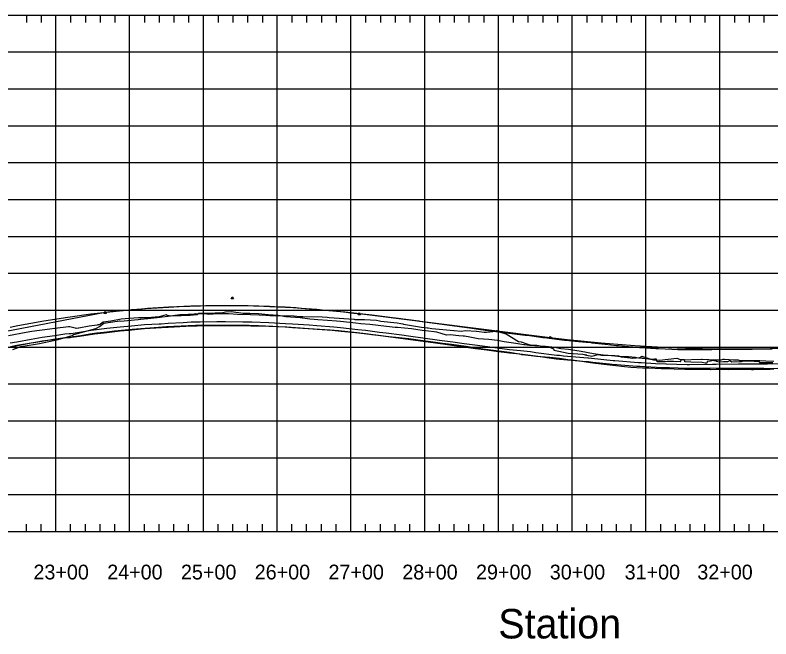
# Model space of a CAD drawing. Extents: x 704797 to 712284, y 374940 to 376945.
# Drawn here: x 709378 to 710403, y 375080 to 375925 of the extents above; entities that cross this region are included whole.
import ezdxf

# ---------------------------------------------------------------- set-up
doc = ezdxf.new("R2010")
doc.units = 0
for name, color, linetype in [('1', 7, 'Continuous'), ('10', 7, 'Continuous'), ('12', 7, 'Continuous'), ('13', 7, 'Continuous'), ('48', 7, 'Continuous'), ('61', 7, 'Continuous'), ('Existing', 7, 'Continuous')]:
    doc.layers.add(name, color=color, linetype=linetype)

msp = doc.modelspace()

# ---------------------------------------------------------------- linework, layer by layer
for points in [[(709672.8, 375543.7), (709674.3, 375540.7), (709671.3, 375540.7)], [(709500.5, 375524.2), (709502, 375521.2), (709499, 375521.2)], [(709845, 375522.3), (709846.5, 375519.3), (709843.5, 375519.3)], [(710104, 375490.1), (710105.5, 375487.1), (710102.5, 375487.1)]]:
    msp.add_lwpolyline(points, close=True)
at = {"layer": '10'}
for points in [[(710405.5, 375454.1), (710393.5, 375453.9), (710387.9, 375453.9), (710387.8, 375454.5), (710387.4, 375455.9), (710385.3, 375455.8), (710384.3, 375455.8), (710380.7, 375455.9), (710379.4, 375456.3), (710376.9, 375456.2), (710369.3, 375456.3), (710365.8, 375456.3), (710363, 375455.4), (710350.1, 375455.1), (710347.4, 375456.7), (710346.7, 375456.7), (710346.1, 375456.5), (710344.2, 375455.3), (710342.9, 375455.3), (710339, 375455.3), (710333.1, 375455.2), (710329.8, 375456), (710328.8, 375456.3), (710326.6, 375456.9), (710326.3, 375457), (710325.7, 375457.2), (710325.1, 375457.2), (710324.6, 375457.2), (710321, 375456.5), (710317.5, 375456), (710316.8, 375455.9), (710316.7, 375455.5), (710316.2, 375453.6), (710314.1, 375453.6), (710309.9, 375454.4), (710294.5, 375455.1), (710286.5, 375455.3), (710286.4, 375455.6), (710286.3, 375456), (710285.9, 375458), (710284.6, 375458.2), (710283.8, 375458.3), (710282.8, 375458.4), (710280.9, 375458.3), (710280.4, 375456), (710280.4, 375455.7), (710280.3, 375455.6), (710271.2, 375455.9), (710262.5, 375455.8), (710259.7, 375455.4), (710251.2, 375455.5), (710248.9, 375455.5), (710248.7, 375455.6), (710248.5, 375456.6), (710248, 375458.3), (710247.8, 375458.9), (710247.6, 375459), (710246.9, 375459.1), (710246.6, 375459), (710246.1, 375459), (710245.3, 375459), (710245.1, 375459), (710241.1, 375458.6), (710240.1, 375458.8), (710238.8, 375459), (710237.3, 375459.2), (710230.4, 375459.8), (710228.7, 375459.9), (710225.6, 375460.4), (710223.4, 375460.5), (710221.3, 375460.9), (710219.7, 375461.3), (710210, 375462.3), (710209.3, 375462.4), (710209.1, 375462.4), (710209, 375462.4), (710208.8, 375462.4), (710202.5, 375462.1), (710201.9, 375462.1), (710201.4, 375462.1), (710201, 375462.1), (710200.6, 375462.1), (710200.3, 375462.1), (710182.4, 375463.9), (710181.6, 375463.9), (710181, 375464), (710175.8, 375464.7), (710162.7, 375466.5), (710145.8, 375469.6), (710128.9, 375472), (710118.2, 375473), (710109.9, 375474.9), (710106, 375475.4), (710105.7, 375475.4), (710097.5, 375476.2), (710076, 375477.4), (710069.7, 375478.3), (710068.1, 375478.3), (710057.5, 375480.4), (710041.7, 375482.4), (710032.5, 375484.3), (710020.7, 375485.8), (710006.4, 375486.8), (709995.1, 375489), (709987.5, 375490.1), (709985.7, 375490.4), (709980, 375490.9), (709968.2, 375492.2), (709963.1, 375491.7), (709950.4, 375495.7), (709935.4, 375497.4), (709930.3, 375497.8), (709915.9, 375500.1), (709896.7, 375502.1), (709893.9, 375501.8), (709893.6, 375501.9), (709882.1, 375503.5), (709870.8, 375504.6), (709859.3, 375505.9), (709847, 375507.2), (709840.6, 375507.9), (709819.4, 375510.1), (709814, 375510.6), (709801.9, 375511.5), (709788.8, 375512.5), (709783.8, 375512.8), (709777.8, 375513.2), (709765.1, 375515.1), (709745.3, 375516.6), (709735.3, 375518.3), (709721.5, 375519), (709708.3, 375520.5), (709696.8, 375521), (709687.7, 375521), (709671.2, 375523.2), (709663.8, 375522.7), (709658.3, 375521.4), (709649.8, 375521.4), (709627.2, 375521.2), (709625.1, 375519), (709615.8, 375518.5), (709603.9, 375518.1), (709602.9, 375518), (709590.3, 375517.4), (709584.5, 375518.2), (709583.1, 375519), (709573.9, 375516.5), (709557.8, 375515.2), (709545.9, 375515), (709533.1, 375514.2), (709522.3, 375513.1), (709508, 375510.8), (709497.9, 375509.2), (709497.7, 375509.2), (709494, 375506.6), (709492.2, 375505.6), (709490.4, 375505.4), (709489.6, 375505.2), (709479, 375503.7), (709464.7, 375501.2), (709464.3, 375501.2), (709461.3, 375500.5), (709460.4, 375501), (709458.2, 375501.6), (709452.8, 375503.1), (709450.8, 375502.8), (709432.4, 375500.5), (709425.7, 375499.6), (709401, 375496.4), (709393.5, 375495.2), (709369.5, 375490.7)], [(709375.2, 375472.3), (709386.3, 375476.2), (709389.3, 375476.6), (709411.6, 375480.5), (709424.1, 375483.1), (709437, 375485.6), (709455.7, 375491.3), (709457.7, 375492.3), (709458.1, 375492.4), (709487.8, 375500.8), (709489.8, 375501.5), (709493, 375503.2), (709498.8, 375507.7), (709517, 375510.4), (709517.2, 375510.5), (709519.8, 375510.9), (709521.3, 375510.8), (709545.4, 375513), (709547.9, 375513.1), (709549.1, 375513.2), (709558.5, 375514.3), (709575, 375516.2), (709577.7, 375516.5), (709585.8, 375517.2), (709601.7, 375519.6), (709604.6, 375519.8), (709621, 375520.5), (709623.1, 375520.8), (709638.3, 375520.6), (709641.3, 375520.3), (709653.5, 375520.9), (709667.3, 375520.8), (709667.6, 375520.8), (709680.1, 375520), (709697.6, 375519.6), (709709.1, 375519.4), (709718.5, 375518.8), (709723.7, 375518.5), (709724, 375518.5), (709733.5, 375518.4), (709756.1, 375517.6), (709764.6, 375517.1), (709768.3, 375517.1), (709794.6, 375516.3), (709801.3, 375515.8), (709804, 375515.6), (709837.5, 375513.1), (709838.2, 375513.1), (709839, 375513), (709841.4, 375512.7), (709852.3, 375512.7), (709868.4, 375511.9), (709872.5, 375511), (709874.2, 375510.8), (709896.6, 375508.3), (709901.3, 375507.6), (709903.9, 375507.1), (709905, 375506.7), (709929.2, 375502.3), (709936.9, 375501.7), (709938.6, 375501.4), (709943.6, 375500.6), (709973.1, 375497.8), (709973.9, 375498), (709983.1, 375496.9), (709989, 375497.9), (710003.8, 375497), (710007.5, 375496.4), (710014.4, 375495.6), (710017.7, 375495.6), (710030.5, 375497.1), (710031.6, 375498.1), (710031.9, 375498), (710033.1, 375496.4), (710042.3, 375494), (710044, 375493.2), (710045.7, 375492.7), (710053.5, 375487.4), (710058.5, 375484.5), (710060.7, 375483.2), (710064.5, 375482.8), (710072.3, 375479.7), (710075, 375479.1), (710077.2, 375478.5), (710084.3, 375478.2), (710085.6, 375478), (710096.7, 375476), (710097, 375476.5), (710099.9, 375475.5), (710101.9, 375475.8), (710108.5, 375473), (710108.7, 375471.7), (710108.8, 375471.1), (710115.5, 375469.8), (710128.1, 375467.3), (710148.3, 375465.9), (710150.1, 375465.4), (710151.2, 375465.1), (710152.1, 375464.8), (710152.2, 375464.8), (710152.2, 375464.8), (710152.4, 375465.2), (710152.6, 375465.5), (710153.1, 375464.7), (710153.2, 375464.5), (710160.2, 375463.3), (710168.9, 375465.2), (710173.3, 375464.7), (710178.4, 375464.4), (710191.3, 375464.1), (710196.7, 375463.6), (710200.3, 375462.3), (710201, 375462.3), (710215.7, 375460.6), (710225.4, 375461.3), (710228.3, 375463.2), (710240.5, 375459.3), (710244, 375458), (710252, 375457.6), (710275.7, 375460.3), (710275.7, 375460.3), (710281.5, 375458.3), (710308.8, 375459.2), (710309.5, 375459.2), (710310.1, 375459.1), (710328.1, 375458.4), (710335.7, 375458.1), (710338.5, 375459.2), (710340.4, 375459.1), (710346.6, 375458.8), (710352.4, 375458.4), (710358.7, 375458.1), (710360.7, 375457.5), (710366.8, 375457.2), (710369.6, 375457.3), (710386.1, 375457.4), (710388.1, 375457.4), (710396, 375456.9), (710407.1, 375456.3)]]:
    msp.add_lwpolyline(points, dxfattribs=at)
at = {"layer": '12'}
for points in [[(709371.9, 375481.1), (709380.6, 375482.8), (709400.4, 375486.2), (709415, 375488.9), (709432.1, 375491.2), (709446, 375493.3), (709451.6, 375493.7), (709452.9, 375493.8), (709454.3, 375494.1), (709468.4, 375496.2), (709484.1, 375498.7), (709485.3, 375498.9), (709503, 375500.9), (709520.9, 375502.9), (709536.1, 375504.1), (709553.9, 375506), (709573.6, 375507.1), (709576.5, 375507.2), (709586.1, 375507.8), (709606.4, 375509), (709617.2, 375509.5), (709629.2, 375509.7), (709652, 375510.1), (709663.8, 375510), (709687.4, 375509.8), (709699.4, 375509.5), (709722.6, 375508.9), (709744.8, 375507.6), (709754.6, 375507.1), (709777.1, 375505.6), (709787.7, 375504.7), (709810.4, 375502.8), (709819.7, 375502), (709842.9, 375499.4), (709853.4, 375498.2), (709872.5, 375495.9), (709881.5, 375494.8), (709902.9, 375491.9), (709911.7, 375490.7), (709953.8, 375485), (709964.7, 375483.5), (709971.7, 375482.5), (709971.8, 375482.5), (709987.4, 375480.5), (710001.6, 375478.6), (710018.9, 375476.2), (710032.1, 375474.6), (710048.9, 375472.4), (710063.5, 375470.9), (710077.1, 375469.4), (710084.2, 375468.3), (710112.7, 375464.6), (710116, 375464.4), (710116.4, 375464.5), (710116.7, 375464.3), (710122, 375463.8), (710149.7, 375461.4), (710155, 375461.1), (710155.4, 375461), (710155.7, 375460.9), (710159.8, 375460.5), (710189.4, 375457.5), (710191.6, 375457.3), (710223.6, 375454.5), (710224.6, 375454.5), (710227, 375454.4), (710246.7, 375453.4), (710260.6, 375452.7), (710261.5, 375452.7), (710289.4, 375451.9), (710292.7, 375451.9), (710324.1, 375452.4), (710328.9, 375452.4), (710359.1, 375452.6), (710365.6, 375452.6), (710384, 375452.7), (710392, 375452.8), (710398.4, 375452.9), (710414.3, 375453.1)], [(709372.3, 375476.2), (709380.6, 375477.9), (709400.2, 375481.2), (709410.4, 375483.1), (709415, 375483.9), (709433.1, 375486.1), (709445.5, 375488), (709451.8, 375488.3), (709453.3, 375488.4), (709454.9, 375488.9), (709465.9, 375490.4), (709486.3, 375493.5), (709499.1, 375494.9), (709521.1, 375497.5), (709532.1, 375498.4), (709553.7, 375500.7), (709577.1, 375501.9), (709585.9, 375502.5), (709610.1, 375503.8), (709617.4, 375504.2), (709624.5, 375504.3), (709625.2, 375504.3), (709652.2, 375504.9), (709661.1, 375504.8), (709687.5, 375504.6), (709698.1, 375504.4), (709722.5, 375503.9), (709744.4, 375502.7), (709754.6, 375502.1), (709775.6, 375500.8), (709788.1, 375499.8), (709808.2, 375498.2), (709820.5, 375497.2), (709839.8, 375495.1), (709855.2, 375493.4), (709862.1, 375492.6), (709870.3, 375491.6), (709884, 375489.9), (709901.1, 375487.5), (709914.4, 375485.8), (709948.6, 375481.1), (709964.6, 375478.9), (709970.3, 375478.1), (709983.6, 375476.3), (710002.7, 375473.7), (710017.8, 375471.6), (710033.7, 375469.6), (710048.9, 375467.6), (710062.7, 375466.1), (710077.2, 375464.4), (710083.8, 375463.4), (710112.1, 375459.6), (710115.6, 375459.4), (710116, 375459.5), (710116.4, 375459.3), (710122.2, 375458.7), (710147.6, 375456.5), (710154.9, 375456), (710155.5, 375455.8), (710155.8, 375455.7), (710161.9, 375455.1), (710184.1, 375452.9), (710187.7, 375452.5), (710194, 375451.9), (710221.2, 375449.5), (710225.9, 375449.4), (710255.1, 375447.9), (710260.6, 375447.6), (710265.6, 375447.7), (710288.9, 375447), (710295.1, 375446.8), (710321.4, 375447.2), (710329.1, 375446.9), (710348.3, 375446.9), (710353.7, 375446.9), (710364.1, 375446.8), (710371, 375446.8), (710393.5, 375446.9), (710398.3, 375446.5), (710399.3, 375446.5), (710412.7, 375446.7)]]:
    msp.add_lwpolyline(points, dxfattribs=at)
at = {"layer": '13'}
msp.add_lwpolyline([(710407.2, 375445.3), (710402.2, 375445.2), (710401.5, 375445.1), (710379.6, 375444.9), (710379, 375444.8), (710378.8, 375444.8), (710377.9, 375444.7), (710377.2, 375444.6), (710376.6, 375444.7), (710369.7, 375445), (710346.1, 375444.8), (710339.9, 375445), (710321.7, 375444.8), (710320.9, 375444.9), (710311.8, 375445.1), (710304.3, 375445.1), (710294.9, 375445.1), (710286.2, 375445.2), (710272, 375445.7), (710263.8, 375445.8), (710254.2, 375446.2), (710237.8, 375446.8), (710237.1, 375446.8), (710231, 375446.9), (710230, 375446.9), (710228.9, 375446.9), (710213, 375447.9), (710204.8, 375448.9), (710189, 375450.7), (710176.8, 375451.9), (710161.6, 375453.7), (710146.6, 375455.9), (710133.6, 375457.6), (710127.9, 375458.3), (710116.4, 375459.8), (710103.2, 375461.5), (710102.9, 375461.5), (710085.3, 375462.5), (710066.9, 375464.9), (710065.6, 375464.9), (710064.4, 375465.2), (710048.7, 375468.3), (710030.8, 375470.5), (710012.6, 375472.8), (709989.9, 375476.2), (709970.1, 375479), (709958, 375480.5), (709945.1, 375482.3), (709928.1, 375484.6), (709912.4, 375486.5), (709894.6, 375488.4), (709885.3, 375489.5), (709849.9, 375493.8), (709838, 375495.2), (709816.8, 375497.3), (709805.6, 375498.3), (709783.9, 375499.7), (709770.8, 375500.8), (709746.8, 375502.5), (709735.6, 375503.1), (709727.8, 375503.5), (709708.4, 375504.4), (709695.6, 375504.7), (709672.1, 375504.8), (709659.4, 375504.9), (709635.5, 375504.9), (709623.4, 375504.7), (709623.2, 375504.6), (709593.5, 375503.5), (709583.6, 375502.9), (709572.8, 375502.2), (709548.7, 375500.3), (709537.1, 375499.4), (709513.4, 375497.1), (709502.8, 375495.8), (709490, 375494.3), (709489.3, 375494.2), (709479.9, 375492.9), (709467.6, 375490.7), (709457.3, 375489.2), (709455.9, 375488.9), (709454.2, 375488.5), (709452.7, 375488.7), (709430.6, 375485.7), (709420, 375484.1), (709403.7, 375481.1), (709400.4, 375480.6), (709389.1, 375478.5), (709367.6, 375474.3)], dxfattribs=at)
at = {"layer": '48'}
for p, q in [((709177, 375460.6), (709500.5, 375522.7)), ((709845, 375520.8), (710104, 375488.6))]:
    msp.add_line(p, q, dxfattribs=at)
for points in [[(709500.5, 375522.7), (709507.7, 375523.5), (709514.9, 375524.2), (709522.1, 375524.9), (709529.3, 375525.6), (709536.4, 375526.3), (709543.6, 375526.9), (709550.8, 375527.5), (709558, 375528), (709565.1, 375528.5), (709572.3, 375529), (709579.5, 375529.5), (709586.7, 375529.9), (709593.8, 375530.2), (709601, 375530.6), (709608.2, 375530.9), (709615.4, 375531.1), (709622.5, 375531.3), (709629.7, 375531.5), (709636.9, 375531.7), (709644.1, 375531.8), (709651.2, 375531.9), (709658.4, 375532), (709665.6, 375532), (709679.9, 375531.9), (709687.1, 375531.8), (709694.3, 375531.7), (709701.5, 375531.5), (709708.7, 375531.3), (709715.8, 375531.1), (709723, 375530.8), (709730.2, 375530.5), (709737.4, 375530.1), (709744.5, 375529.8), (709751.7, 375529.4), (709758.9, 375528.9), (709766.1, 375528.4), (709773.2, 375527.9), (709780.4, 375527.4), (709787.6, 375526.8), (709794.8, 375526.1), (709801.9, 375525.5), (709809.1, 375524.8), (709816.3, 375524.1), (709823.5, 375523.3), (709830.6, 375522.5), (709837.8, 375521.6), (709845, 375520.8)], [(710104, 375488.6), (710126.9, 375485.9), (710149.9, 375483.4), (710172.8, 375481.2), (710195.7, 375479.3), (710218.6, 375477.6), (710241.5, 375476.2), (710264.4, 375475.1), (710287.4, 375474.2), (710310.3, 375473.5), (710333.2, 375473.2), (710356.1, 375473.1), (710379, 375473.2), (710401.9, 375473.6), (710424.9, 375474.3)]]:
    msp.add_lwpolyline(points, dxfattribs=at)
at = {"layer": '61'}
for p, q in [((708133.7, 375925.5), (712133.7, 375925.5)), ((709393.7, 375925.5), (709393.7, 375915.5)), ((709413.7, 375925.5), (709413.7, 375915.5)), ((709433.7, 375225.5), (709433.7, 375925.5)), ((709453.7, 375925.5), (709453.7, 375915.5)), ((709473.7, 375925.5), (709473.7, 375915.5)), ((709493.7, 375925.5), (709493.7, 375915.5)), ((709513.7, 375925.5), (709513.7, 375915.5)), ((709533.7, 375225.5), (709533.7, 375925.5)), ((709553.7, 375925.5), (709553.7, 375915.5)), ((709573.7, 375925.5), (709573.7, 375915.5)), ((709593.7, 375925.5), (709593.7, 375915.5)), ((709613.7, 375925.5), (709613.7, 375915.5)), ((709633.7, 375225.5), (709633.7, 375925.5)), ((709653.7, 375925.5), (709653.7, 375915.5)), ((709673.7, 375925.5), (709673.7, 375915.5)), ((709693.7, 375925.5), (709693.7, 375915.5)), ((709713.7, 375925.5), (709713.7, 375915.5)), ((709733.7, 375225.5), (709733.7, 375925.5)), ((709753.7, 375925.5), (709753.7, 375915.5)), ((709773.7, 375925.5), (709773.7, 375915.5)), ((709793.7, 375925.5), (709793.7, 375915.5)), ((709813.7, 375925.5), (709813.7, 375915.5)), ((709833.7, 375225.5), (709833.7, 375925.5)), ((709853.7, 375925.5), (709853.7, 375915.5)), ((709873.7, 375925.5), (709873.7, 375915.5)), ((709893.7, 375925.5), (709893.7, 375915.5)), ((709913.7, 375925.5), (709913.7, 375915.5)), ((709933.7, 375225.5), (709933.7, 375925.5)), ((709953.7, 375925.5), (709953.7, 375915.5)), ((709973.7, 375925.5), (709973.7, 375915.5)), ((709993.7, 375925.5), (709993.7, 375915.5)), ((710013.7, 375925.5), (710013.7, 375915.5)), ((710033.7, 375225.5), (710033.7, 375925.5)), ((710053.7, 375925.5), (710053.7, 375915.5)), ((710073.7, 375925.5), (710073.7, 375915.5)), ((710093.7, 375925.5), (710093.7, 375915.5)), ((710113.7, 375925.5), (710113.7, 375915.5)), ((710133.7, 375225.5), (710133.7, 375925.5)), ((710153.7, 375925.5), (710153.7, 375915.5)), ((710173.7, 375925.5), (710173.7, 375915.5)), ((710193.7, 375925.5), (710193.7, 375915.5)), ((710213.7, 375925.5), (710213.7, 375915.5)), ((710233.7, 375225.5), (710233.7, 375925.5)), ((710253.7, 375925.5), (710253.7, 375915.5)), ((710273.7, 375925.5), (710273.7, 375915.5)), ((710293.7, 375925.5), (710293.7, 375915.5)), ((710313.7, 375925.5), (710313.7, 375915.5)), ((710333.7, 375225.5), (710333.7, 375925.5)), ((710353.7, 375925.5), (710353.7, 375915.5)), ((710373.7, 375925.5), (710373.7, 375915.5)), ((710393.7, 375925.5), (710393.7, 375915.5)), ((708133.7, 375875.5), (712133.7, 375875.5)), ((708133.7, 375825.5), (712133.7, 375825.5)), ((708133.7, 375775.5), (712133.7, 375775.5)), ((708133.7, 375725.5), (712133.7, 375725.5)), ((708133.7, 375675.5), (712133.7, 375675.5)), ((708133.7, 375625.5), (712133.7, 375625.5)), ((708133.7, 375575.5), (712133.7, 375575.5)), ((708133.7, 375525.5), (712133.7, 375525.5)), ((708133.7, 375475.5), (712133.7, 375475.5)), ((708133.7, 375425.5), (712133.7, 375425.5)), ((708133.7, 375375.5), (712133.7, 375375.5)), ((708133.7, 375325.5), (712133.7, 375325.5)), ((708133.7, 375275.5), (712133.7, 375275.5)), ((709393.7, 375225.5), (709393.7, 375235.5)), ((709413.7, 375225.5), (709413.7, 375235.5)), ((709453.7, 375225.5), (709453.7, 375235.5)), ((709473.7, 375225.5), (709473.7, 375235.5)), ((709493.7, 375225.5), (709493.7, 375235.5)), ((709513.7, 375225.5), (709513.7, 375235.5)), ((709553.7, 375225.5), (709553.7, 375235.5)), ((709573.7, 375225.5), (709573.7, 375235.5)), ((709593.7, 375225.5), (709593.7, 375235.5)), ((709613.7, 375225.5), (709613.7, 375235.5)), ((709653.7, 375225.5), (709653.7, 375235.5)), ((709673.7, 375225.5), (709673.7, 375235.5)), ((709693.7, 375225.5), (709693.7, 375235.5)), ((709713.7, 375225.5), (709713.7, 375235.5)), ((709753.7, 375225.5), (709753.7, 375235.5)), ((709773.7, 375225.5), (709773.7, 375235.5)), ((709793.7, 375225.5), (709793.7, 375235.5)), ((709813.7, 375225.5), (709813.7, 375235.5)), ((709853.7, 375225.5), (709853.7, 375235.5)), ((709873.7, 375225.5), (709873.7, 375235.5)), ((709893.7, 375225.5), (709893.7, 375235.5)), ((709913.7, 375225.5), (709913.7, 375235.5)), ((709953.7, 375225.5), (709953.7, 375235.5)), ((709973.7, 375225.5), (709973.7, 375235.5)), ((709993.7, 375225.5), (709993.7, 375235.5)), ((710013.7, 375225.5), (710013.7, 375235.5)), ((710053.7, 375225.5), (710053.7, 375235.5)), ((710073.7, 375225.5), (710073.7, 375235.5)), ((710093.7, 375225.5), (710093.7, 375235.5)), ((710113.7, 375225.5), (710113.7, 375235.5)), ((710153.7, 375225.5), (710153.7, 375235.5)), ((710173.7, 375225.5), (710173.7, 375235.5)), ((710193.7, 375225.5), (710193.7, 375235.5)), ((710213.7, 375225.5), (710213.7, 375235.5)), ((710253.7, 375225.5), (710253.7, 375235.5)), ((710273.7, 375225.5), (710273.7, 375235.5)), ((710293.7, 375225.5), (710293.7, 375235.5)), ((710313.7, 375225.5), (710313.7, 375235.5)), ((710353.7, 375225.5), (710353.7, 375235.5)), ((710373.7, 375225.5), (710373.7, 375235.5)), ((710393.7, 375225.5), (710393.7, 375235.5)), ((708133.7, 375225.5), (712133.7, 375225.5))]:
    msp.add_line(p, q, dxfattribs=at)
at = {"layer": 'Existing'}
msp.add_lwpolyline([(709371.6, 375502.6), (709382.1, 375504.6), (709382.2, 375504.7), (709417.5, 375511.2), (709417.5, 375511.2), (709450, 375516.1), (709450.1, 375516.1), (709450.1, 375516.1), (709450.1, 375516.1), (709450.1, 375516.1), (709481.3, 375520.5), (709481.3, 375520.5), (709481.3, 375520.5), (709481.3, 375520.5), (709519.8, 375524.8), (709554.6, 375527.6), (709555.1, 375527.7), (709587, 375529.7), (709597.6, 375530.3), (709616.5, 375531.2), (709649.6, 375531.9), (709650.4, 375531.9), (709684.9, 375531.7), (709686, 375531.7), (709722.1, 375530.8), (709723.1, 375530.8), (709724, 375530.7), (709755.6, 375528.9), (709756.4, 375528.9), (709792.4, 375525.9), (709793.1, 375525.9), (709825.1, 375523.1), (709825.4, 375523.1), (709862.1, 375519), (709862.1, 375519), (709893.8, 375515.2), (709894.2, 375515.1), (709925.7, 375511), (709926.7, 375510.8), (709964.1, 375505.6), (709964.2, 375505.6), (709964.3, 375505.6), (709997.8, 375501), (710009.2, 375499.4), (710010, 375499.3), (710015.8, 375498.6), (710033.9, 375496.3), (710047.6, 375494.5), (710048.2, 375494.5), (710048.7, 375494.4), (710049.7, 375494.3), (710052, 375494), (710070.1, 375491.7), (710075.6, 375491), (710088.1, 375489.4), (710094.1, 375488.6), (710095.1, 375488.5), (710095.2, 375488.6), (710095.6, 375488.6), (710106.2, 375487.1), (710123.3, 375484.8), (710124.3, 375484.7), (710124.5, 375484.7), (710142.3, 375483.1), (710152.8, 375482.2), (710155, 375482), (710155.1, 375482), (710158.9, 375481.6), (710160.4, 375481.4), (710178.5, 375479.4), (710186.2, 375478.5), (710186.7, 375478.4), (710193.2, 375477.8), (710196.5, 375477.5), (710214.6, 375475.7), (710215.9, 375475.6), (710217.1, 375475.5), (710232.7, 375474.5), (710247.1, 375473.6), (710247.3, 375473.6), (710250.7, 375473.5), (710268.8, 375472.7), (710277, 375472.3), (710277.8, 375472.3), (710286.9, 375472.3), (710304.9, 375472.3), (710311.1, 375472.3), (710312.3, 375472.3), (710323, 375472.4), (710341.1, 375472.5), (710343.6, 375472.5), (710344.8, 375472.5), (710359.1, 375472.6), (710376.8, 375472.7), (710377.2, 375472.7), (710377.6, 375472.7), (710395.3, 375472.9), (710404.9, 375473)], dxfattribs=at)

# ---------------------------------------------------------------- texts
at = {"layer": '1'}
msp.add_text('Station', height=40, dxfattribs=at).set_placement((710033.5, 375080.5))
at = {"layer": '61'}
for s, p in [('23+00', (709403.3, 375160.5)), ('24+00', (709503.3, 375160.5)), ('25+00', (709603.3, 375160.5)), ('26+00', (709703.3, 375160.5)), ('27+00', (709803.3, 375160.5)), ('28+00', (709903.3, 375160.5)), ('29+00', (710003.3, 375160.5)), ('30+00', (710103.3, 375160.5)), ('31+00', (710204.8, 375160.5)), ('32+00', (710303.3, 375160.5))]:
    msp.add_text(s, height=20, dxfattribs=at).set_placement(p)

doc.saveas('drawing.dxf')
